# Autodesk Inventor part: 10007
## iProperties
Shininess: 86.0
Length Units: 11272
Angle Units: 11279
Time Units: 11290
Mass Units: 11286
Length Display Precision: 3
Angle Display Precision: 2
Created: 2002-04
Part Number: 10007
Material: Stainless Steel, Austenitic
Description: Globe, Captive Panel Screw, 6-32 UNC x 0.7813 in
Document SubType Name: Modeling
Designer: CM
Density: 10.49
Volumn: 2.304646865681294
Area: 8.437628188859923
PropertySet Name: Model Information
Control State: 0
Master: False
Checked Out: False
Author: CM
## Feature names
1. Head [Extrusion]
2. Shank [Extrusion]
3. Thd Body [Extrusion]
4. Thd Chamf [Chamfer]
5. Point [Revolution]
6. Knurl [Extrusion]
7. Head Chamf [Chamfer]
8. Slot [Extrusion]
